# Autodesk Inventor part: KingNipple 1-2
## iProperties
Company: Mountain Blue Industries Ltd.
Category: Plumbing
Manager: CBliss
Shininess: 64.0
Length Units: 11272
Angle Units: 11279
Time Units: 11290
Mass Units: 11286
Length Display Precision: 3
Angle Display Precision: 2
Compacted: True
Part Number: KingNipple 1-2
Document SubType Name: Modeling
Created: 2003-03
Designer: QBZ
Material: Steel, Mild
Description: 1/2 NPT King Nipple
Density: 0.0
Volumn: 0.0
Area: 0.0
PropertySet Name: Model Information
Control State: 0
Master: False
Checked Out: False
Length: 1
Author: QBZ
Revision Number: A
Title: King Nipple
Subject: iPart Creation
Keywords: Fittings
Comments: Looking for additional sizes 2-1/2, 3, 4, and 6 inch NPT.
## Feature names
1. Revolution1
